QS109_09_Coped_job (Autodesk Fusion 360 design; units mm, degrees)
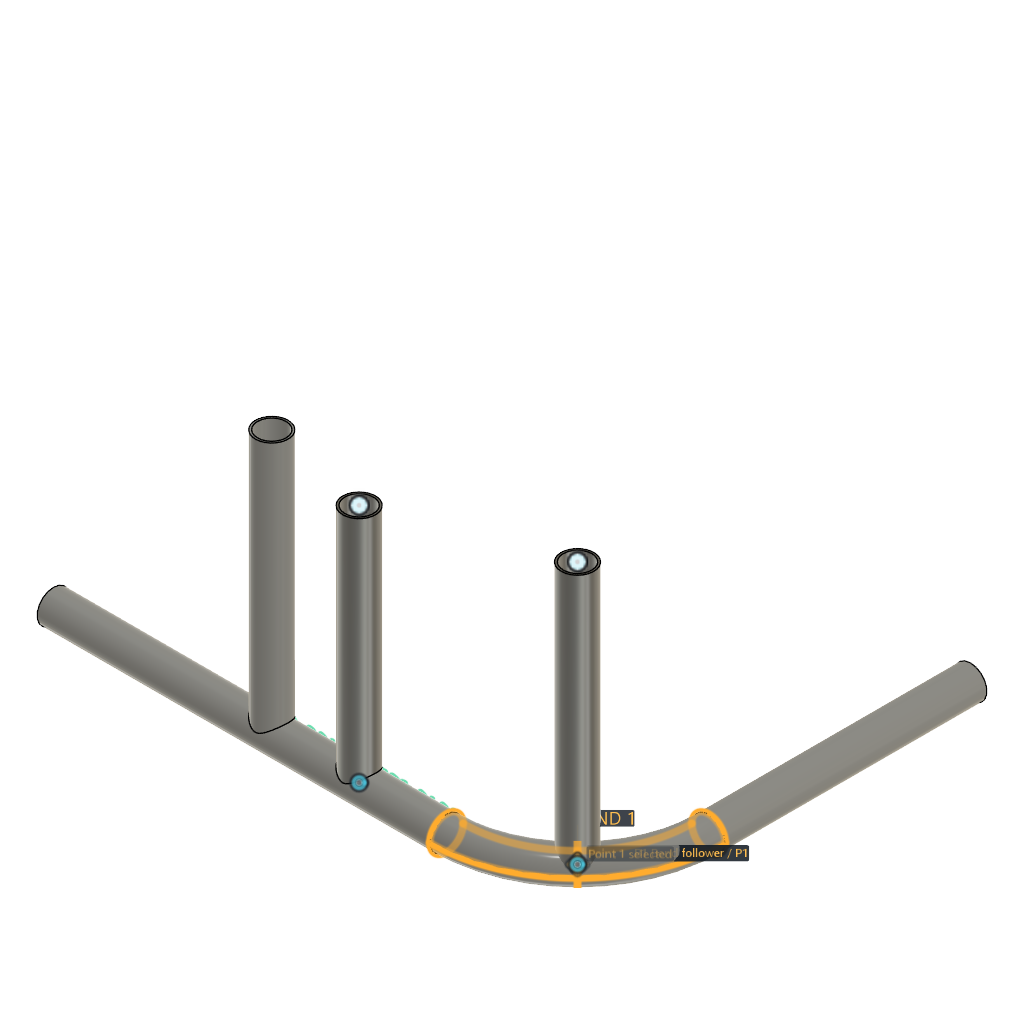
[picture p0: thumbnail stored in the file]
description: Part Number
part number: 2026-10-26-11-38-19-526
parameter "OD_DEMO_ONLY_1_5_x_095_R6" = 38.1
parameter "Wall_DEMO_ONLY_1_5_x_095_R6" = 2.413
base_feature "Base Feature1" bodies "H1 Bent host", "I1 Imported coped brace"
sketch "Tube points" plane through (0, 0, 0) normal (0, 0, 1) x axis (1, 0, 0)
sketch "TubePoints" plane through (0, 0, 0) normal (0, 0, 1) x axis (1, 0, 0)
work_plane "WorkPlane1" ExtraOffset 0
sketch "Sketch3" plane through (564.9631, 44.6369, 0) normal (0, 0, 1) x axis (0, 1, 0)
  circle C1 centre (0, 0) radius 19.05
  circle C2 centre (0, 0) radius 16.637
sketch "TubePoints (1)" plane through (0, 0, 0) normal (0, 0, 1) x axis (1, 0, 0)
work_plane "WorkPlane2" ExtraOffset 0
sketch "Sketch5" plane through (355.6, 0, 0) normal (0, 0, 1) x axis (0, 1, 0)
  circle C1 centre (0, 0) radius 19.05
  circle C2 centre (0, 0) radius 16.637
sketch "TubePoints (2)" plane through (0, 0, 0) normal (0, 0, 1) x axis (1, 0, 0)
work_plane "WorkPlane3" ExtraOffset 0
sketch "Sketch7" plane through (564.9631, 44.6369, 0) normal (0, 0, 1) x axis (0, 1, 0)
  circle C1 centre (0, 0) radius 19.05
  circle C2 centre (0, 0) radius 16.637
  dimension "d21" diameter C1 = 38.1 (= "OD_DEMO_ONLY_1_5_x_095_R6")
  dimension "d22" diameter C2 = 33.274 (= "OD_DEMO_ONLY_1_5_x_095_R6 - 2 * Wall_DEMO_ONLY_1_5_x_095_R6")
sweep "Sweep3" sketch "Sketch7" TwistAngle 0 TaperAngle 0 bodies "B1 Bend follower"
sketch "TubePoints (3)" plane through (0, 0, 0) normal (0, 0, 1) x axis (1, 0, 0)
work_plane "WorkPlane4" ExtraOffset 0
sketch "Sketch9" plane through (355.6, 0, 0) normal (0, 0, 1) x axis (0, 1, 0)
  circle C1 centre (0, 0) radius 19.05
  circle C2 centre (0, 0) radius 16.637
  dimension "d31" diameter C1 = 38.1 (= "OD_DEMO_ONLY_1_5_x_095_R6")
  dimension "d32" diameter C2 = 33.274 (= "OD_DEMO_ONLY_1_5_x_095_R6 - 2 * Wall_DEMO_ONLY_1_5_x_095_R6")
sweep "Sweep4" sketch "Sketch9" TwistAngle 0 TaperAngle 0 bodies "B2 Straight joint"
base_feature "Base Feature2"
surface_stitch "SurfaceStitch1" StitchingTolerence 0.01 bodies "normcope_B2_Straight_joint_A"
split "Split1" bodies "B2 Straight joint"
remove_body "RemoveBody1"
remove_body "RemoveBody2"
named bodies: "H1 Bent host", "I1 Imported coped brace", "B1 Bend follower", "B2 Straight joint", "normcope_B2_Straight_joint_A"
